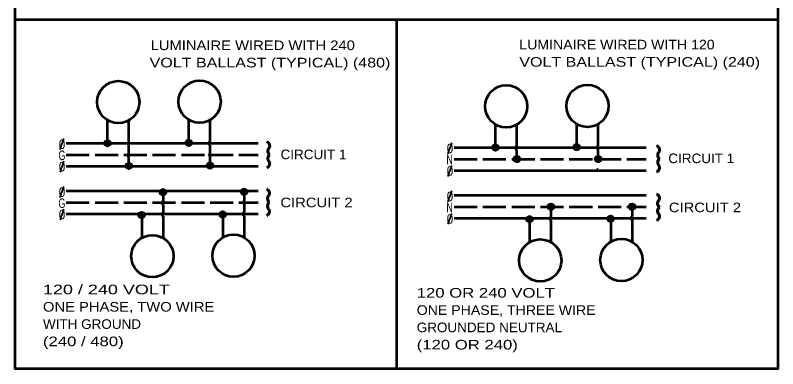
# Model space of a CAD drawing. Extents: x -153 to 527, y -247 to 194.
# Drawn here: x 201.1 to 399.7, y 11.2 to 103.1 of the extents above; entities that cross this region are included whole.
import ezdxf

# ---------------------------------------------------------------- set-up
doc = ezdxf.new("R2010")
doc.units = 0
doc.linetypes.add('LONG_DASHED', pattern=[7.5, 6, -1.5])
doc.layers.add('1', color=7, linetype='Continuous', lineweight=53)

msp = doc.modelspace()

# ---------------------------------------------------------------- hatches: boundary and pattern name
at = {"layer": '1'}
for points in [[(332.491, 65.716, 1), (330.991, 65.716, 1)], [(353.661, 65.716, 1), (352.161, 65.716, 1)], [(341.369, 53.316, 1), (339.869, 53.316, 1)], [(362.501, 53.316, 1), (361.001, 53.316, 1)]]:
    msp.add_hatch(color=256, dxfattribs=at).paths.add_polyline_path(points)

# ---------------------------------------------------------------- linework, layer by layer
for p, q in [((201.088, 102.029), (399.686, 102.029)), ((300.387, 102.029), (300.387, 11.168)), ((225.14, 69.731), (225.14, 75.79)), ((225.14, 69.731), (225.14, 75.79)), ((230.705, 70.131), (230.705, 75.79)), ((246.31, 69.838), (246.31, 75.897)), ((246.31, 69.838), (246.31, 75.897)), ((251.875, 70.238), (251.875, 75.897)), ((326.176, 68.617), (326.176, 74.676)), ((326.176, 68.617), (326.176, 74.676)), ((331.741, 69.017), (331.741, 74.676)), ((347.346, 68.724), (347.346, 74.783)), ((347.346, 68.724), (347.346, 74.783)), ((352.911, 69.124), (352.911, 74.783)), ((214.365, 69.83), (264.365, 69.83)), ((214.365, 69.83), (264.365, 69.83)), ((230.705, 67.112), (230.705, 69.256)), ((251.875, 67.219), (251.875, 69.362)), ((315.402, 68.716), (365.402, 68.716)), ((315.402, 68.716), (365.402, 68.716)), ((331.741, 65.716), (331.741, 68.142)), ((352.911, 65.716), (352.911, 68.248)), ((230.705, 63.854), (230.705, 66.232)), ((230.705, 63.854), (230.705, 66.232)), ((251.875, 63.961), (251.875, 66.339)), ((251.875, 63.961), (251.875, 66.339)), ((214.365, 63.83), (264.365, 63.83)), ((214.365, 63.83), (264.365, 63.83)), ((315.402, 62.716), (365.402, 62.716)), ((315.402, 62.716), (365.402, 62.716)), ((214.365, 57.43), (264.365, 57.43)), ((214.365, 57.43), (264.365, 57.43)), ((239.583, 57.132), (239.583, 54.754)), ((239.583, 57.132), (239.583, 54.754)), ((260.715, 57.255), (260.715, 54.877)), ((260.715, 57.255), (260.715, 54.877)), ((315.402, 56.316), (365.402, 56.316)), ((315.402, 56.316), (365.402, 56.316)), ((239.583, 53.874), (239.583, 51.73)), ((260.715, 53.997), (260.715, 51.853)), ((340.619, 53.316), (340.619, 50.616)), ((361.751, 53.316), (361.751, 50.739)), ((214.365, 51.43), (264.365, 51.43)), ((214.365, 51.43), (264.365, 51.43)), ((234.018, 51.255), (234.018, 45.196)), ((234.018, 51.255), (234.018, 45.196)), ((239.583, 50.855), (239.583, 45.196)), ((255.15, 51.378), (255.15, 45.319)), ((260.715, 50.978), (260.715, 45.319)), ((315.402, 50.316), (365.402, 50.316)), ((315.402, 50.316), (365.402, 50.316)), ((335.054, 50.141), (335.054, 44.082)), ((335.054, 50.141), (335.054, 44.082)), ((340.619, 49.741), (340.619, 44.082)), ((356.186, 50.264), (356.186, 44.205)), ((361.751, 49.864), (361.751, 44.205))]:
    msp.add_line(p, q, dxfattribs=at)
at = {"layer": '1', "lineweight": 35}
for p, q in [((213.732, 71.021), (212.701, 68.189)), ((314.768, 69.907), (313.737, 67.075)), ((213.781, 65.163), (212.75, 62.331)), ((314.818, 64.049), (313.786, 61.216)), ((213.732, 58.568), (212.701, 55.735)), ((314.768, 57.427), (313.737, 54.595)), ((213.781, 52.71), (212.75, 49.877)), ((314.818, 51.569), (313.786, 48.736))]:
    msp.add_line(p, q, dxfattribs=at)
at = {"layer": '1', "linetype": 'LONG_DASHED'}
for p, q in [((214.365, 66.83), (264.365, 66.83)), ((214.365, 66.83), (264.365, 66.83)), ((315.402, 65.716), (365.402, 65.716)), ((315.402, 65.716), (365.402, 65.716)), ((214.365, 54.43), (264.365, 54.43)), ((214.365, 54.43), (264.365, 54.43)), ((315.402, 53.316), (365.402, 53.316)), ((315.402, 53.316), (365.402, 53.316))]:
    msp.add_line(p, q, dxfattribs=at)
at = {"layer": '1'}
msp.add_lwpolyline([(201.088, 110.53), (399.686, 110.53), (399.686, 11.168), (201.088, 11.168)], close=True, dxfattribs=at)
for centre, radius in [((227.923, 80.535), 5.5), ((249.093, 80.641), 5.5), ((328.959, 79.421), 5.5), ((350.129, 79.527), 5.5), ((225.106, 69.827), 0.75), ((225.106, 69.841), 0.724), ((225.106, 69.827), 0.698), ((225.099, 69.827), 0.67), ((225.093, 69.841), 0.636), ((225.082, 69.865), 0.606), ((225.072, 69.882), 0.575), ((225.069, 69.895), 0.55), ((225.062, 69.885), 0.517), ((225.055, 69.902), 0.482), ((225.048, 69.895), 0.455), ((225.038, 69.93), 0.424), ((225.031, 69.936), 0.397), ((225.017, 69.943), 0.357), ((225.021, 69.943), 0.333), ((225.014, 69.971), 0.297), ((225.004, 69.988), 0.267), ((225, 69.995), 0.236), ((224.997, 69.998), 0.205), ((224.987, 69.998), 0.174), ((224.973, 70.001), 0.133), ((224.973, 70.001), 0.0993), ((224.976, 69.998), 0.0548), ((224.97, 70.005), 0.0208), ((246.276, 69.933), 0.75), ((246.276, 69.947), 0.724), ((246.276, 69.933), 0.698), ((246.27, 69.933), 0.67), ((246.263, 69.947), 0.636), ((246.252, 69.971), 0.606), ((246.242, 69.988), 0.575), ((246.239, 70.002), 0.55), ((246.232, 69.992), 0.517), ((246.225, 70.009), 0.482), ((246.218, 70.002), 0.455), ((246.208, 70.036), 0.424), ((246.201, 70.043), 0.397), ((246.188, 70.05), 0.357), ((246.191, 70.05), 0.333), ((246.184, 70.077), 0.297), ((246.174, 70.094), 0.267), ((246.17, 70.101), 0.236), ((246.167, 70.104), 0.205), ((246.157, 70.104), 0.174), ((246.143, 70.108), 0.133), ((246.143, 70.108), 0.0993), ((246.147, 70.104), 0.0548), ((246.14, 70.111), 0.0208), ((347.313, 68.819), 0.75), ((347.313, 68.833), 0.724), ((347.313, 68.819), 0.698), ((326.143, 68.713), 0.75), ((326.143, 68.727), 0.724), ((326.143, 68.713), 0.698), ((326.136, 68.713), 0.67), ((326.129, 68.727), 0.636), ((326.119, 68.751), 0.606), ((326.108, 68.768), 0.575), ((326.105, 68.781), 0.55), ((326.098, 68.771), 0.517), ((326.091, 68.788), 0.482), ((326.085, 68.781), 0.455), ((326.074, 68.816), 0.424), ((326.067, 68.822), 0.397), ((326.054, 68.829), 0.357), ((326.057, 68.829), 0.333), ((326.05, 68.857), 0.297), ((326.04, 68.874), 0.267), ((326.037, 68.88), 0.236), ((326.033, 68.884), 0.205), ((326.023, 68.884), 0.174), ((326.009, 68.887), 0.133), ((326.009, 68.887), 0.0993), ((326.013, 68.884), 0.0548), ((326.006, 68.891), 0.0208), ((347.306, 68.819), 0.67), ((347.299, 68.833), 0.636), ((347.289, 68.857), 0.606), ((347.279, 68.874), 0.575), ((347.275, 68.888), 0.55), ((347.268, 68.877), 0.517), ((347.261, 68.895), 0.482), ((347.255, 68.888), 0.455), ((347.244, 68.922), 0.424), ((347.238, 68.929), 0.397), ((347.224, 68.936), 0.357), ((347.227, 68.936), 0.333), ((347.22, 68.963), 0.297), ((347.21, 68.98), 0.267), ((347.207, 68.987), 0.236), ((347.203, 68.99), 0.205), ((347.193, 68.99), 0.174), ((347.179, 68.994), 0.133), ((347.179, 68.994), 0.0993), ((347.183, 68.99), 0.0548), ((347.176, 68.997), 0.0208), ((331.741, 65.716), 0.75), ((352.911, 65.716), 0.75), ((230.671, 63.921), 0.75), ((230.671, 63.921), 0.75), ((230.671, 63.935), 0.724), ((230.671, 63.935), 0.724), ((230.671, 63.921), 0.698), ((230.664, 63.921), 0.67), ((230.658, 63.935), 0.636), ((230.647, 63.959), 0.606), ((230.637, 63.976), 0.575), ((230.634, 63.99), 0.55), ((230.627, 63.98), 0.517), ((230.62, 63.997), 0.482), ((230.613, 63.99), 0.455), ((230.603, 64.024), 0.424), ((230.596, 64.031), 0.397), ((230.582, 64.038), 0.357), ((230.586, 64.038), 0.333), ((230.579, 64.065), 0.297), ((230.569, 64.082), 0.267), ((230.565, 64.089), 0.236), ((230.562, 64.092), 0.205), ((230.552, 64.092), 0.174), ((230.552, 64.092), 0.138), ((230.552, 64.092), 0.118), ((230.552, 64.092), 0.113), ((230.552, 64.092), 0.0924), ((230.552, 64.092), 0.0708), ((230.552, 64.092), 0.0567), ((230.552, 64.092), 0.0474), ((230.552, 64.092), 0.0415), ((230.552, 64.092), 0.0359), ((230.552, 64.092), 0.0359), ((230.552, 64.092), 0.0335), ((251.841, 64.027), 0.75), ((251.841, 64.027), 0.75), ((251.841, 64.041), 0.724), ((251.841, 64.041), 0.724), ((251.841, 64.028), 0.698), ((251.834, 64.028), 0.67), ((251.828, 64.041), 0.636), ((251.817, 64.065), 0.606), ((251.807, 64.082), 0.575), ((251.804, 64.096), 0.55), ((251.797, 64.086), 0.517), ((251.79, 64.103), 0.482), ((251.783, 64.096), 0.455), ((251.773, 64.13), 0.424), ((251.766, 64.137), 0.397), ((251.752, 64.144), 0.357), ((251.756, 64.144), 0.333), ((251.749, 64.171), 0.297), ((251.739, 64.188), 0.267), ((251.735, 64.195), 0.236), ((251.732, 64.199), 0.205), ((251.722, 64.199), 0.174), ((251.722, 64.199), 0.15), ((251.722, 64.199), 0.143), ((251.722, 64.199), 0.129), ((251.722, 64.199), 0.117), ((251.722, 64.199), 0.0983), ((251.722, 64.199), 0.0775), ((251.722, 64.199), 0.0575), ((251.722, 64.199), 0.041), ((251.722, 64.199), 0.0282), ((251.722, 64.199), 0.0266), ((251.722, 64.199), 0.0071), ((352.758, 63.085), 0.0071), ((239.549, 57.065), 0.75), ((239.549, 57.065), 0.75), ((239.549, 57.051), 0.724), ((239.549, 57.051), 0.724), ((239.549, 57.065), 0.698), ((239.542, 57.065), 0.67), ((239.536, 57.051), 0.636), ((239.525, 57.027), 0.606), ((260.681, 57.188), 0.75), ((260.681, 57.188), 0.75), ((260.681, 57.174), 0.724), ((260.681, 57.174), 0.724), ((260.681, 57.188), 0.698), ((260.674, 57.188), 0.67), ((260.668, 57.174), 0.636), ((260.657, 57.15), 0.606), ((260.647, 57.133), 0.575), ((260.644, 57.119), 0.55), ((260.637, 57.13), 0.517), ((260.63, 57.113), 0.482), ((239.515, 57.01), 0.575), ((239.512, 56.997), 0.55), ((239.505, 57.007), 0.517), ((239.498, 56.99), 0.482), ((239.491, 56.997), 0.455), ((239.481, 56.962), 0.424), ((239.474, 56.956), 0.397), ((239.46, 56.949), 0.357), ((239.464, 56.949), 0.333), ((239.457, 56.921), 0.297), ((239.447, 56.904), 0.267), ((239.443, 56.898), 0.236), ((239.44, 56.894), 0.205), ((239.43, 56.894), 0.174), ((239.43, 56.894), 0.138), ((239.43, 56.894), 0.118), ((239.43, 56.894), 0.113), ((239.43, 56.894), 0.0924), ((239.43, 56.894), 0.0708), ((239.43, 56.894), 0.0567), ((239.43, 56.894), 0.0474), ((239.43, 56.894), 0.0415), ((239.43, 56.894), 0.0359), ((239.43, 56.894), 0.0359), ((239.43, 56.894), 0.0335), ((260.623, 57.119), 0.455), ((260.613, 57.085), 0.424), ((260.606, 57.078), 0.397), ((260.592, 57.072), 0.357), ((260.596, 57.072), 0.333), ((260.589, 57.044), 0.297), ((260.579, 57.027), 0.267), ((260.575, 57.02), 0.236), ((260.575, 57.02), 0.202), ((260.575, 57.02), 0.173), ((260.575, 57.02), 0.143), ((260.575, 57.02), 0.104), ((260.575, 57.02), 0.0736), ((260.575, 57.02), 0.046), ((260.575, 57.02), 0.0378), ((340.619, 53.316), 0.75), ((361.751, 53.316), 0.75), ((233.984, 51.16), 0.75), ((233.984, 51.146), 0.724), ((233.984, 51.159), 0.698), ((233.978, 51.159), 0.67), ((233.971, 51.146), 0.636), ((233.96, 51.122), 0.606), ((233.95, 51.105), 0.575), ((233.947, 51.091), 0.55), ((255.116, 51.283), 0.75), ((255.116, 51.268), 0.724), ((255.116, 51.282), 0.698), ((255.109, 51.282), 0.67), ((255.103, 51.268), 0.636), ((255.092, 51.245), 0.606), ((255.082, 51.227), 0.575), ((255.079, 51.214), 0.55), ((255.072, 51.224), 0.517), ((255.065, 51.207), 0.482), ((255.058, 51.214), 0.455), ((233.94, 51.101), 0.517), ((233.933, 51.084), 0.482), ((233.926, 51.091), 0.455), ((233.916, 51.057), 0.424), ((233.909, 51.05), 0.397), ((233.896, 51.043), 0.357), ((233.899, 51.043), 0.333), ((233.892, 51.016), 0.297), ((233.882, 50.999), 0.267), ((233.878, 50.992), 0.236), ((233.875, 50.988), 0.205), ((255.048, 51.18), 0.424), ((255.041, 51.173), 0.397), ((255.027, 51.166), 0.357), ((255.027, 51.166), 0.308), ((255.027, 51.166), 0.306), ((255.027, 51.166), 0.251), ((255.027, 51.166), 0.202), ((255.027, 51.166), 0.169), ((255.027, 51.166), 0.132), ((255.027, 51.166), 0.0892), ((255.027, 51.166), 0.0695), ((255.027, 51.166), 0.0352), ((335.021, 50.046), 0.75), ((335.021, 50.032), 0.724), ((335.021, 50.045), 0.698), ((335.014, 50.045), 0.67), ((335.007, 50.032), 0.636), ((334.997, 50.008), 0.606), ((334.987, 49.99), 0.575), ((334.983, 49.977), 0.55), ((334.976, 49.987), 0.517), ((334.969, 49.97), 0.482), ((334.963, 49.977), 0.455), ((334.952, 49.943), 0.424), ((334.946, 49.936), 0.397), ((334.932, 49.929), 0.357), ((334.935, 49.929), 0.333), ((334.928, 49.902), 0.297), ((334.918, 49.885), 0.267), ((334.915, 49.878), 0.236), ((334.911, 49.874), 0.205), ((356.153, 50.169), 0.75), ((356.153, 50.154), 0.724), ((356.153, 50.168), 0.698), ((356.146, 50.168), 0.67), ((356.139, 50.154), 0.636), ((356.129, 50.13), 0.606), ((356.118, 50.113), 0.575), ((356.115, 50.1), 0.55), ((356.108, 50.11), 0.517), ((356.101, 50.093), 0.482), ((356.095, 50.1), 0.455), ((356.084, 50.066), 0.424), ((356.077, 50.059), 0.397), ((356.064, 50.052), 0.357), ((356.064, 50.052), 0.308), ((356.064, 50.052), 0.306), ((356.064, 50.052), 0.251), ((356.064, 50.052), 0.202), ((356.064, 50.052), 0.169), ((356.064, 50.052), 0.132), ((356.064, 50.052), 0.0892), ((356.064, 50.052), 0.0695), ((356.064, 50.052), 0.0352), ((236.801, 40.452), 5.5), ((257.933, 40.575), 5.5), ((337.837, 39.338), 5.5), ((358.969, 39.461), 5.5)]:
    msp.add_circle(centre, radius, dxfattribs=at)
for centre in [(230.841, 69.696), (252.012, 69.803), (331.878, 68.582), (353.048, 68.689), (230.87, 66.672), (252.04, 66.779), (239.748, 54.314), (260.88, 54.437), (239.72, 51.29), (260.851, 51.413), (340.756, 50.176), (361.888, 50.299)]:
    msp.add_arc(centre, 0.465, 108.90604, 251.09396, dxfattribs=at)
at = {"layer": '1', "lineweight": 60}
for centre, radius, start, end in [((266.226, 69.167), 1.135, 330.39195, 71.42822), ((268.086, 67.781), 1.204, 136.63658, 231.64318), ((367.761, 68.122), 1.135, 330.39195, 71.42822), ((369.621, 66.736), 1.204, 136.63658, 231.64318), ((268.086, 65.893), 1.204, 128.35682, 223.36342), ((369.621, 64.848), 1.204, 128.35682, 223.36342), ((266.226, 64.506), 1.135, 288.57178, 29.60805), ((367.761, 63.462), 1.135, 288.57178, 29.60805), ((266.149, 56.786), 1.135, 330.39195, 71.42822), ((268.009, 55.399), 1.204, 136.63658, 231.64318), ((367.737, 55.505), 1.135, 330.39195, 71.42822), ((268.009, 53.511), 1.204, 128.35682, 223.36342), ((369.597, 54.119), 1.204, 136.63658, 231.64318), ((266.149, 52.125), 1.135, 288.57178, 29.60805), ((369.597, 52.231), 1.204, 128.35682, 223.36342), ((367.737, 50.845), 1.135, 288.57178, 29.60805)]:
    msp.add_arc(centre, radius, start, end, dxfattribs=at)

# ---------------------------------------------------------------- texts
at = {"layer": '1'}
for s, width, p in [('LUMINAIRE WIRED WITH 240', 1.15, (236.35, 94.052)), ('LUMINAIRE WIRED WITH 120', 1.1, (332.372, 94.236)), ('VOLT BALLAST (TYPICAL) (480)', 1.25, (236.087, 89.552)), ('VOLT BALLAST (TYPICAL) (240)', 1.25, (332.372, 89.736)), ('0', 0.9, (212.439, 68.315)), ('0', 0.9, (313.475, 67.201)), ('G', 0.7, (212.338, 65.433)), ('CIRCUIT 1', 1.05, (270.193, 65.669)), ('N', 0.7, (313.375, 64.319)), ('CIRCUIT 1', 1.05, (371.186, 64.644)), ('0', 0.9, (212.439, 62.475)), ('0', 0.9, (313.475, 61.361)), ('0', 0.9, (212.439, 55.862)), ('CIRCUIT 2', 1.15, (270.157, 53.167)), ('0', 0.9, (313.475, 54.721)), ('G', 0.7, (212.338, 52.98)), ('N', 0.7, (313.375, 51.839)), ('CIRCUIT 2', 1.15, (371.332, 51.887)), ('0', 0.9, (212.439, 50.022)), ('0', 0.9, (313.475, 48.881)), ('120 / 240 VOLT', 1.4, (208.302, 30.534)), ('120 OR 240 VOLT', 1.3, (305.659, 29.672)), ('ONE PHASE, TWO WIRE', 1.15, (208.302, 26.034)), ('ONE PHASE, THREE WIRE', 1.1, (305.659, 25.172)), ('WITH GROUND', 1.05, (208.302, 21.534)), ('GROUNDED NEUTRAL', 1.05, (305.659, 20.672)), ('(240 / 480)', 1.3, (208.302, 17.034)), ('(120 OR 240)', 1.3, (305.659, 16.172))]:
    msp.add_text(s, height=2.5, dxfattribs=dict(at, width=width)).set_placement(p)

doc.saveas('drawing.dxf')
